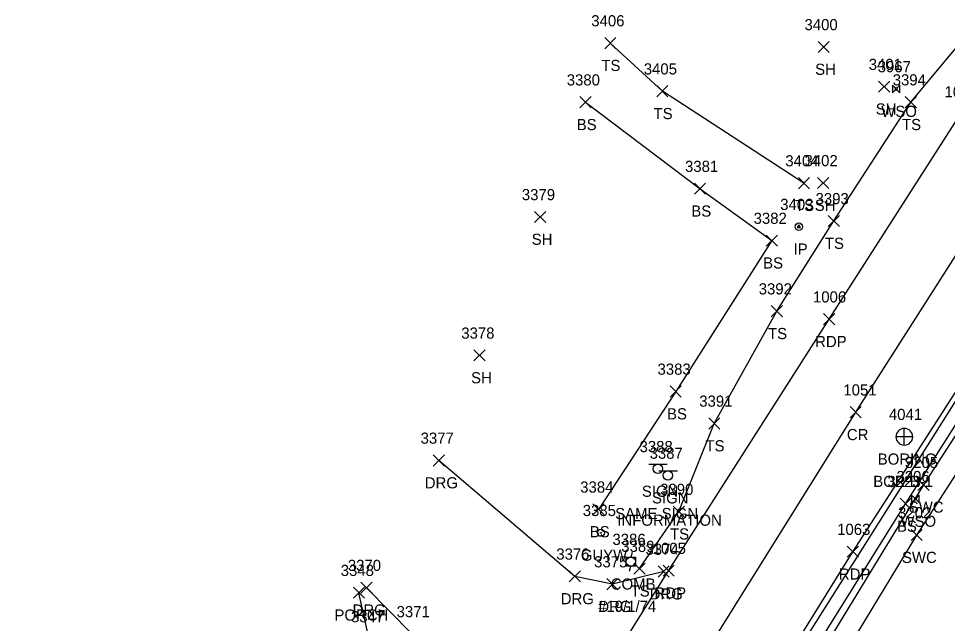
# Model space of a CAD drawing. Extents: x 1634209 to 1639641, y 608564 to 612258.
# Drawn here: x 1638854.8 to 1639021.2, y 611042.5 to 611150.8 of the extents above; entities that cross this region are included whole.
import ezdxf

# ---------------------------------------------------------------- set-up
doc = ezdxf.new("R2010")
doc.units = 0
for name, color, linetype in [('DCP', 7, 'Continuous'), ('G_A', 7, 'Continuous'), ('G_C', 7, 'Continuous'), ('G_I', 7, 'Continuous'), ('GA_P', 7, 'Continuous'), ('L_A', 7, 'Continuous'), ('L_I', 7, 'Continuous'), ('L_TIC', 7, 'Continuous'), ('LBF', 7, 'Continuous'), ('LELB', 7, 'Continuous'), ('M_A', 7, 'Continuous'), ('M_I', 7, 'Continuous'), ('MPIR', 7, 'Continuous'), ('P_A', 7, 'Continuous'), ('P_I', 7, 'Continuous'), ('P_TIC', 7, 'Continuous'), ('PET', 7, 'Continuous'), ('PRC', 7, 'Continuous'), ('R_A', 7, 'Continuous'), ('R_I', 7, 'Continuous'), ('R_TIC', 7, 'Continuous'), ('RDG', 7, 'Continuous'), ('RSW', 7, 'Continuous'), ('S_A', 7, 'Continuous'), ('S_C', 7, 'Continuous'), ('S_I', 7, 'Continuous'), ('SSGN', 7, 'Continuous'), ('U_A', 7, 'Continuous'), ('U_C', 7, 'Continuous'), ('U_I', 7, 'Continuous'), ('UP', 7, 'Continuous'), ('UPGW', 7, 'Continuous'), ('UWV', 7, 'Continuous')]:
    doc.layers.add(name, color=color, linetype=linetype)

msp = doc.modelspace()

# ---------------------------------------------------------------- linework, layer by layer
at = {"layer": 'DCP'}
msp.add_lwpolyline([(1638981.5, 611017.05), (1639053.43, 611130.86)], dxfattribs=at)
at = {"layer": 'GA_P'}
for p, q in [((1639013.51, 611075.91), (1639013.51, 611077.41)), ((1639013.51, 611075.91), (1639012.01, 611075.91)), ((1639015.01, 611075.91), (1639013.51, 611075.91)), ((1639013.51, 611074.41), (1639013.51, 611075.91))]:
    msp.add_line(p, q, dxfattribs=at)
for start, end in [(90, 180), (0, 90), (180, 270), (270, 0)]:
    msp.add_arc((1639013.51, 611075.91), 1.5, start, end, dxfattribs=at)
at = {"layer": 'L_TIC'}
for points in [[(1638959.83, 611145.42), (1638961.83, 611147.42)], [(1638961.83, 611145.42), (1638959.83, 611147.42)], [(1638998.06, 611144.73), (1639000.06, 611146.73)], [(1639000.06, 611144.73), (1638998.06, 611146.73)], [(1638969.17, 611136.8), (1638971.17, 611138.8)], [(1638971.17, 611136.8), (1638969.17, 611138.8)], [(1639008.9, 611137.61), (1639010.9, 611139.61)], [(1639010.9, 611137.61), (1639008.9, 611139.61)], [(1638955.38, 611134.83), (1638957.38, 611136.83)], [(1638957.38, 611134.83), (1638955.38, 611136.83)], [(1639013.69, 611134.84), (1639015.69, 611136.84)], [(1639015.69, 611134.84), (1639013.69, 611136.84)], [(1638994.53, 611120.34), (1638996.53, 611122.34)], [(1638996.53, 611120.34), (1638994.53, 611122.34)], [(1638997.97, 611120.37), (1638999.97, 611122.37)], [(1638999.97, 611120.37), (1638997.97, 611122.37)], [(1638975.91, 611119.34), (1638977.91, 611121.34)], [(1638977.91, 611119.34), (1638975.91, 611121.34)], [(1638947.26, 611114.28), (1638949.26, 611116.28)], [(1638949.26, 611114.28), (1638947.26, 611116.28)], [(1638999.87, 611113.56), (1639001.87, 611115.56)], [(1639001.87, 611113.56), (1638999.87, 611115.56)], [(1638988.77, 611110.04), (1638990.77, 611112.04)], [(1638990.77, 611110.04), (1638988.77, 611112.04)], [(1638989.68, 611097.4), (1638991.68, 611099.4)], [(1638991.68, 611097.4), (1638989.68, 611099.4)], [(1638936.4, 611089.48), (1638938.4, 611091.48)], [(1638938.4, 611089.48), (1638936.4, 611091.48)], [(1638971.56, 611083.02), (1638973.56, 611085.02)], [(1638973.56, 611083.02), (1638971.56, 611085.02)], [(1638978.47, 611077.29), (1638980.47, 611079.29)], [(1638980.47, 611077.29), (1638978.47, 611079.29)], [(1638957.71, 611061.9), (1638959.71, 611063.9)], [(1638959.71, 611061.9), (1638957.71, 611063.9)], [(1639012.75, 611062.89), (1639014.75, 611064.89)], [(1639014.75, 611062.89), (1639012.75, 611064.89)], [(1638972.12, 611061.49), (1638974.12, 611063.49)], [(1638974.12, 611061.49), (1638972.12, 611063.49)], [(1638965.07, 611051.28), (1638967.07, 611053.28)], [(1638967.07, 611051.28), (1638965.07, 611053.28)], [(1638914.8, 611046.97), (1638916.8, 611048.97)], [(1638916.8, 611046.97), (1638914.8, 611048.97)]]:
    msp.add_lwpolyline(points, dxfattribs=at)
at = {"layer": 'LBF'}
msp.add_lwpolyline([(1638894.59, 611002.32), (1638917.64, 611039.67), (1638915.8, 611047.97)], dxfattribs=at)
at = {"layer": 'LELB'}
for points in [[(1638966.07, 611052.28), (1638973.12, 611062.49), (1638979.47, 611078.29), (1638990.68, 611098.4), (1639000.87, 611114.56), (1639014.69, 611135.84), (1639038.15, 611164.03), (1639040.42, 611167.6)], [(1638995.53, 611121.34), (1638970.17, 611137.8), (1638960.83, 611146.42)], [(1638956.38, 611135.83), (1638976.91, 611120.34), (1638989.77, 611111.04), (1638972.56, 611084.02), (1638958.71, 611062.9)], [(1638982.99, 611014.59), (1639013.75, 611063.89), (1639039.18, 611103.98)]]:
    msp.add_lwpolyline(points, dxfattribs=at)
at = {"layer": 'MPIR'}
msp.add_lwpolyline([(1638994.61, 611113.87), (1638994.33, 611113.37), (1638994.9, 611113.37)], close=True, dxfattribs=at)
msp.add_circle((1638994.61, 611113.53), 0.667, dxfattribs=at)
at = {"layer": 'P_TIC'}
for points in [[(1638999.04, 611095.96), (1639001.04, 611097.96)], [(1639001.04, 611095.96), (1638999.04, 611097.96)], [(1639003.79, 611079.3), (1639005.79, 611081.3)], [(1639005.79, 611079.3), (1639003.79, 611081.3)], [(1639003.29, 611054.32), (1639005.29, 611056.32)], [(1639005.29, 611054.32), (1639003.29, 611056.32)], [(1638970.29, 611050.92), (1638972.29, 611052.92)], [(1638972.29, 611050.92), (1638970.29, 611052.92)]]:
    msp.add_lwpolyline(points, dxfattribs=at)
at = {"layer": 'PET'}
for points in [[(1638854.83, 610853.22), (1638885.37, 610909), (1638902.82, 610937.28), (1638929.33, 610982.56), (1638950.92, 611019.42), (1638971.29, 611051.92), (1639000.04, 611096.96), (1639023.57, 611133.7), (1639039.12, 611159.19), (1639064.62, 611197.78), (1639080.51, 611223.3), (1639114.23, 611277.34), (1639131.17, 611302.28), (1639149.64, 611331.79), (1639176.42, 611372.35), (1639193.48, 611398.88), (1639220.96, 611441.47), (1639247.22, 611483.75)], [(1638878.4, 610839.82), (1638902.26, 610883.1), (1638925.76, 610925.06), (1638957.25, 610978.12), (1638978.73, 611014.12), (1639004.29, 611055.32), (1639040.97, 611112.28), (1639073.41, 611162.89), (1639072.72, 611163.46), (1639102.57, 611207.56), (1639124.27, 611240.99), (1639140.69, 611264.29), (1639156.2, 611287.4), (1639175.63, 611318.1), (1639189.77, 611341.61), (1639219.88, 611389.38), (1639245.26, 611428.04), (1639265.27, 611462.65)]]:
    msp.add_lwpolyline(points, dxfattribs=at)
at = {"layer": 'PRC'}
msp.add_lwpolyline([(1639250.46, 611462.84), (1639222.36, 611418.18), (1639195.34, 611376.28), (1639169.71, 611336.75), (1639147.17, 611302.78), (1639120.59, 611261.16), (1639092.55, 611217.83), (1639063.71, 611172.41), (1639032.46, 611123.7), (1639004.79, 611080.3), (1638977.88, 611037.27), (1638950.44, 610992.13), (1638925.96, 610950.29), (1638900.29, 610905.36), (1638879.75, 610869.2), (1638867.15, 610846.08)], dxfattribs=at)
at = {"layer": 'R_TIC'}
for points in [[(1638929.11, 611070.66), (1638931.11, 611072.66)], [(1638931.11, 611070.66), (1638929.11, 611072.66)], [(1639015.95, 611066.31), (1639017.95, 611068.31)], [(1639017.95, 611066.31), (1639015.95, 611068.31)], [(1639014.73, 611057.3), (1639016.73, 611059.3)], [(1639016.73, 611057.3), (1639014.73, 611059.3)], [(1638969.4, 611050.76), (1638971.4, 611052.76)], [(1638971.4, 611050.76), (1638969.4, 611052.76)], [(1638953.47, 611049.9), (1638955.47, 611051.9)], [(1638955.47, 611049.9), (1638953.47, 611051.9)], [(1638916.17, 611047.87), (1638918.17, 611049.87)], [(1638918.17, 611047.87), (1638916.17, 611049.87)], [(1638960.2, 611048.51), (1638962.2, 611050.51)], [(1638962.2, 611048.51), (1638960.2, 611050.51)]]:
    msp.add_lwpolyline(points, dxfattribs=at)
at = {"layer": 'RDG'}
for points in [[(1638970.4, 611051.76), (1638961.2, 611049.51), (1638954.47, 611050.9), (1638930.11, 611071.66)], [(1638917.17, 611048.87), (1638925.25, 611040.58), (1638942.49, 611029.8), (1638949.04, 611016.65)]]:
    msp.add_lwpolyline(points, dxfattribs=at)
at = {"layer": 'RSW'}
for points in [[(1639042.52, 611106.87), (1639016.95, 611067.31), (1638996.03, 611033.02), (1638978.68, 611004.78), (1638963.33, 610979.05), (1638946.23, 610950.27), (1638931.64, 610924.09), (1638919.4, 610902.22), (1638904.83, 610875.98), (1638895.3, 610858.44), (1638883.54, 610836.57)], [(1638887.24, 610836.54), (1638902.8, 610864.3), (1638908.08, 610874.62), (1638910.81, 610879.12), (1638923.92, 610902.1), (1638938.05, 610928.02), (1638949.86, 610948.73), (1638968.01, 610979.25), (1638983.29, 611004.79), (1638997.34, 611027.92), (1639015.73, 611058.3), (1639044.74, 611103.21)]]:
    msp.add_lwpolyline(points, dxfattribs=at)
at = {"layer": 'SSGN'}
for p, q in [((1638967.71, 611071), (1638971.04, 611071)), ((1638969.36, 611070.17), (1638969.36, 611070.17)), ((1638969.51, 611069.81), (1638972.85, 611069.81)), ((1638971.16, 611068.98), (1638971.16, 611068.98))]:
    msp.add_line(p, q, dxfattribs=at)
for centre in [(1638969.36, 611070.17), (1638971.16, 611068.98)]:
    msp.add_circle(centre, 0.833, dxfattribs=at)
at = {"layer": 'UP'}
for p, q in [((1638963.7, 611052.7), (1638963.7, 611054.36)), ((1638963.7, 611054.36), (1638965.36, 611054.36)), ((1638964.78, 611055.2), (1638964.53, 611054.36)), ((1638965.36, 611054.36), (1638965.36, 611052.7)), ((1638965.36, 611052.7), (1638963.7, 611052.7)), ((1638964.28, 611051.86), (1638964.53, 611052.7)), ((1638964.53, 611053.53), (1638964.53, 611053.53))]:
    msp.add_line(p, q, dxfattribs=at)
msp.add_circle((1638964.53, 611053.53), 0.833, dxfattribs=at)
at = {"layer": 'UPGW'}
for radius in [0.625, 0.0833]:
    msp.add_circle((1638959.16, 611058.7), radius, dxfattribs=at)
at = {"layer": 'UWV'}
for p, q in [((1639011.38, 611138.87), (1639011.93, 611138.32)), ((1639012.71, 611138.87), (1639012.16, 611138.32)), ((1639011.93, 611138.08), (1639011.38, 611137.53)), ((1639012.16, 611138.08), (1639012.71, 611137.53)), ((1639014.82, 611065.44), (1639015.37, 611064.89)), ((1639015.37, 611064.66), (1639014.82, 611064.11)), ((1639016.16, 611065.44), (1639015.61, 611064.89)), ((1639015.61, 611064.66), (1639016.16, 611064.11))]:
    msp.add_line(p, q, dxfattribs=at)
for points in [[(1639011.38, 611138.87), (1639011.38, 611137.53)], [(1639012.71, 611137.53), (1639012.71, 611138.87)], [(1639014.82, 611065.44), (1639014.82, 611064.11)], [(1639016.16, 611064.11), (1639016.16, 611065.44)]]:
    msp.add_lwpolyline(points, dxfattribs=at)
for points in [[(1639012.28, 611138.2), (1639012.05, 611138.44), (1639011.81, 611138.2), (1639012.05, 611137.96)], [(1639015.73, 611064.78), (1639015.49, 611065.01), (1639015.25, 611064.78), (1639015.49, 611064.54)]]:
    msp.add_lwpolyline(points, close=True, dxfattribs=at)

# ---------------------------------------------------------------- texts
at = {"layer": 'G_A'}
msp.add_text('BORING', height=2, dxfattribs=at).set_placement((1639008.75, 611070.91))
at = {"layer": 'G_C'}
msp.add_text('BOR B-1', height=2, dxfattribs=at).set_placement((1639007.94, 611066.91))
at = {"layer": 'G_I'}
msp.add_text('4041', height=2, dxfattribs=at).set_placement((1639010.74, 611078.91))
at = {"layer": 'L_A'}
for s, p in [('TS', (1638959.23, 611141.42)), ('SH', (1638997.54, 611140.73)), ('SH', (1639008.39, 611133.61)), ('TS', (1638968.58, 611132.8)), ('BS', (1638954.82, 611130.83)), ('TS', (1639013.1, 611130.84)), ('BS', (1638975.35, 611115.34)), ('TS', (1638993.94, 611116.34)), ('SH', (1638997.46, 611116.37)), ('SH', (1638946.75, 611110.28)), ('TS', (1638999.28, 611109.56)), ('BS', (1638988.21, 611106.04)), ('TS', (1638989.09, 611093.4)), ('SH', (1638935.89, 611085.48)), ('BS', (1638971, 611079.02)), ('TS', (1638977.88, 611073.29)), ('BS', (1639012.19, 611058.89)), ('BS', (1638957.16, 611057.9)), ('TS', (1638971.53, 611057.49)), ('TS', (1638964.48, 611047.28)), ('PORCH', (1638911.42, 611042.97))]:
    msp.add_text(s, height=2, dxfattribs=at).set_placement(p)
at = {"layer": 'L_I'}
for s, p in [('3406', (1638957.43, 611149.42)), ('3400', (1638995.63, 611148.73)), ('3405', (1638966.83, 611140.8)), ('3401', (1639007.13, 611141.61)), ('3380', (1638953.03, 611138.83)), ('3394', (1639011.43, 611138.84)), ('3404', (1638992.19, 611124.34)), ('3402', (1638995.63, 611124.37)), ('3381', (1638974.22, 611123.34)), ('3379', (1638944.99, 611118.28)), ('3393', (1638997.61, 611117.56)), ('3382', (1638986.51, 611114.04)), ('3392', (1638987.42, 611101.4)), ('3378', (1638934.14, 611093.48)), ('3383', (1638969.3, 611087.02)), ('3391', (1638976.77, 611081.29)), ('3223', (1639010.49, 611066.89)), ('3384', (1638955.45, 611065.9)), ('3390', (1638969.77, 611065.49)), ('3389', (1638962.8, 611055.28)), ('3348', (1638912.54, 611050.97)), ('3347', (1638914.38, 611042.67))]:
    msp.add_text(s, height=2, dxfattribs=at).set_placement(p)
at = {"layer": 'M_A'}
msp.add_text('IP', height=2, dxfattribs=at).set_placement((1638993.66, 611108.53))
at = {"layer": 'M_I'}
msp.add_text('3403', height=2, dxfattribs=at).set_placement((1638991.28, 611116.53))
at = {"layer": 'P_A'}
for s, p in [('RDP', (1638997.53, 611091.96)), ('CR', (1639003.22, 611075.3)), ('RDP', (1639001.78, 611050.32)), ('RDP', (1638968.77, 611046.92))]:
    msp.add_text(s, height=2, dxfattribs=at).set_placement(p)
at = {"layer": 'P_I'}
for s, p in [('1007', (1639020.72, 611136.7)), ('1006', (1638997.14, 611099.96)), ('1051', (1639002.59, 611083.3)), ('1063', (1639001.48, 611058.32)), ('1005', (1638968.43, 611054.92))]:
    msp.add_text(s, height=2, dxfattribs=at).set_placement(p)
at = {"layer": 'R_A'}
for s, p in [('DRG', (1638927.6, 611066.66)), ('SWC', (1639014.31, 611062.31)), ('SWC', (1639013.09, 611053.3)), ('DRG', (1638951.96, 611045.9)), ('DRG', (1638967.89, 611046.76)), ('DRG', (1638914.66, 611043.87)), ('DRG', (1638958.69, 611044.51))]:
    msp.add_text(s, height=2, dxfattribs=at).set_placement(p)
at = {"layer": 'R_I'}
for s, p in [('3377', (1638926.85, 611074.66)), ('3205', (1639013.61, 611070.31)), ('3202', (1639012.39, 611061.3)), ('3376', (1638951.16, 611053.9)), ('3374', (1638967.14, 611054.76)), ('3370', (1638913.82, 611051.87)), ('3375', (1638957.94, 611052.51)), ('3371', (1638922.55, 611043.58))]:
    msp.add_text(s, height=2, dxfattribs=at).set_placement(p)
at = {"layer": 'S_A'}
for p in [(1638966.49, 611065.15), (1638968.3, 611063.96)]:
    msp.add_text('SIGN', height=2, dxfattribs=at).set_placement(p)
at = {"layer": 'S_C'}
for s, p in [('SAME SIGN', (1638961.71, 611061.15)), ('INFORMATION', (1638962.09, 611059.96))]:
    msp.add_text(s, height=2, dxfattribs=at).set_placement(p)
at = {"layer": 'S_I'}
for s, p in [('3388', (1638966.08, 611073.15)), ('3387', (1638967.88, 611071.96))]:
    msp.add_text(s, height=2, dxfattribs=at).set_placement(p)
at = {"layer": 'U_A'}
for s, p in [('WSO', (1639009.38, 611133.2)), ('WSO', (1639012.82, 611059.78)), ('GUYW', (1638955.55, 611053.7)), ('COMB', (1638960.92, 611048.53))]:
    msp.add_text(s, height=2, dxfattribs=at).set_placement(p)
at = {"layer": 'U_C'}
msp.add_text('#19/1/74', height=2, dxfattribs=at).set_placement((1638958.66, 611044.53))
at = {"layer": 'U_I'}
for s, p in [('3967', (1639008.74, 611141.2)), ('3206', (1639012.1, 611067.78)), ('3385', (1638955.9, 611061.7)), ('3386', (1638961.22, 611056.53))]:
    msp.add_text(s, height=2, dxfattribs=at).set_placement(p)

doc.saveas('drawing.dxf')
